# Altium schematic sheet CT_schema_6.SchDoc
size 205 x 258 mm
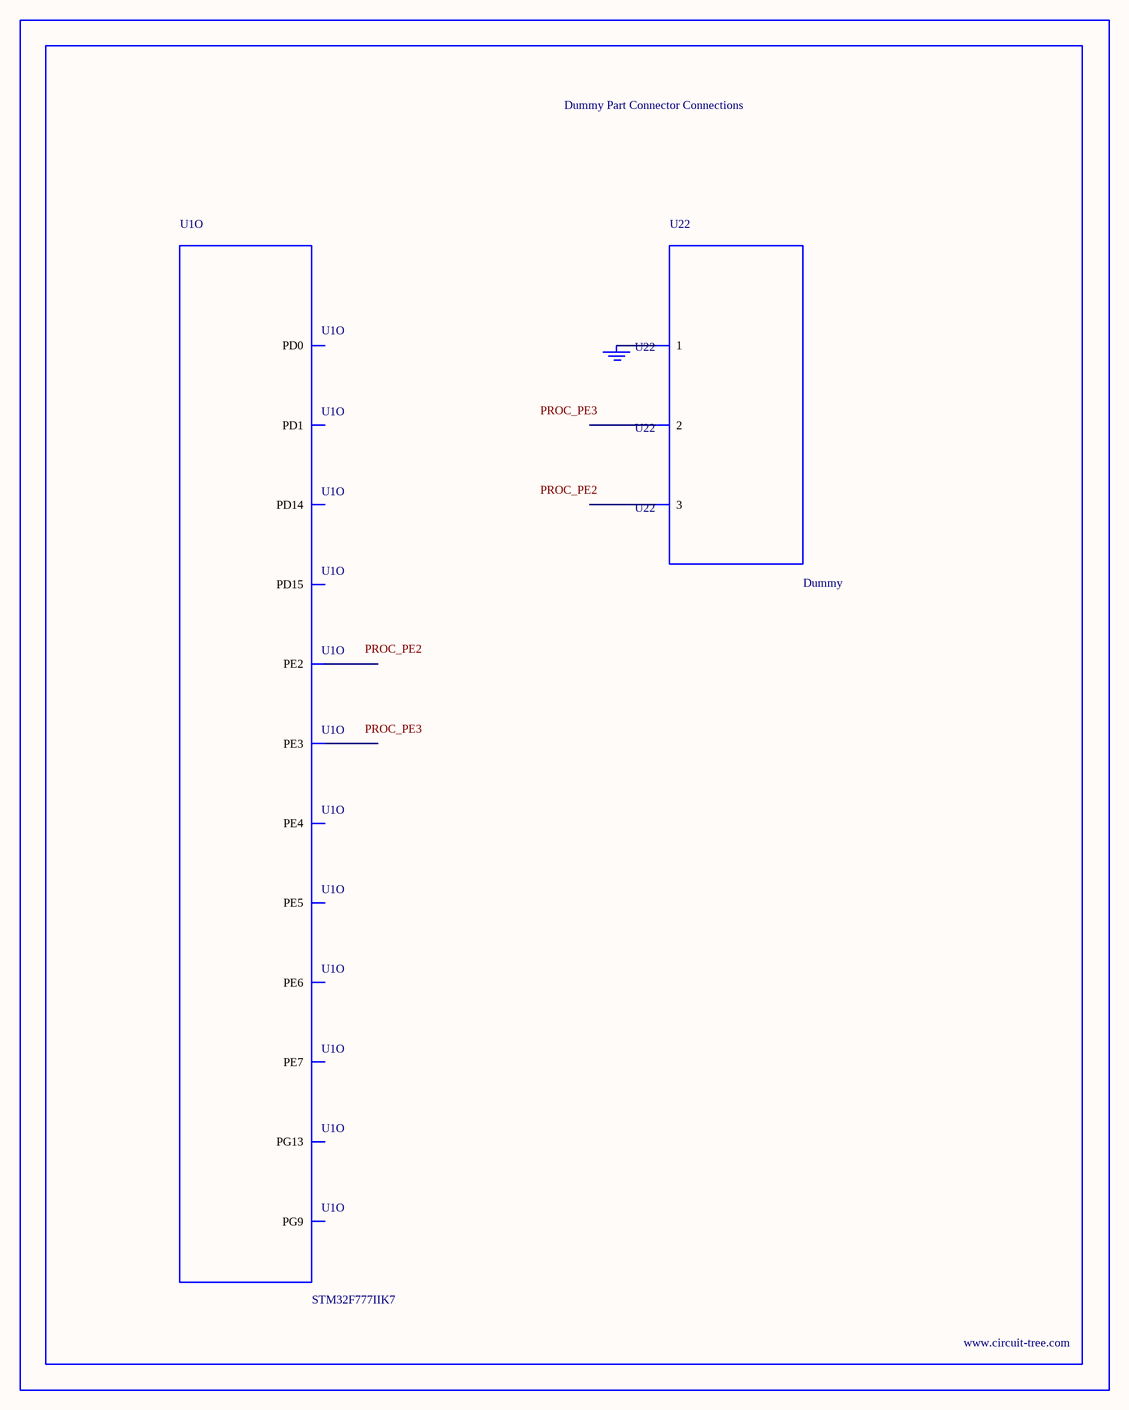
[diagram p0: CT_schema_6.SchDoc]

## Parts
BORDER5  (no value)
GND_INSTANCE_5_0  (no value)
U1  STM32F777IIK7  [UFBGA176_25]  (part O of 15)
U22  Dummy  [DUMMY_PACKAGE_318]

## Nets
NetGND_INSTANCE_5_0_0: GND_INSTANCE_5_0.0(GND) U22.1

Not connected (* = marked no-connect by the designer): U1 A1(PE3) A2(PE2) A8(PG13) B1(PE4) B2(PE5) B3(PE6) B12(PD0) C10(PG9) C12(PD1) L14(PD15) M14(PD14) R8(PE7); U22 2 3

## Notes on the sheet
- Labels drawn without touching a wire or pin: PROC_PE2, PROC_PE3

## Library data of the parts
BORDER5 = BORDER_PAGE5
GND_INSTANCE_5_0 = GND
